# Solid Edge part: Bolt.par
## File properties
Author: Sarvanan
Template: Sync Iso Part.par
Last saved by: Sarvanan
Revision: 5
Application: Solid Edge
Accuracy: 0.990
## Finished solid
Body 1: solid body, 12 faces, 22 edges, 12 vertices.
  Faces by surface: plane 7, spun 4, cylinder 1
  Edges by curve: line 8, circle 7, intersection 7
Bounding box of the edges (mm; curved faces can reach further): 24.000 x 24.000 x 104.000, from (0, -2.3071, 0) to (24, 21.6929, 104).
Cylindrical faces by radius (mm): R6 x1
Planar faces by outward normal: +x 1, +y 1, +z 2, -x 1, -y 1, -z 1
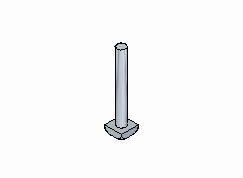
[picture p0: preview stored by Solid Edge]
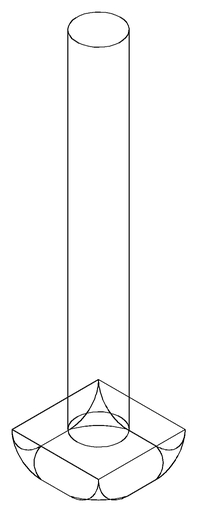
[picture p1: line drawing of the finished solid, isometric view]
